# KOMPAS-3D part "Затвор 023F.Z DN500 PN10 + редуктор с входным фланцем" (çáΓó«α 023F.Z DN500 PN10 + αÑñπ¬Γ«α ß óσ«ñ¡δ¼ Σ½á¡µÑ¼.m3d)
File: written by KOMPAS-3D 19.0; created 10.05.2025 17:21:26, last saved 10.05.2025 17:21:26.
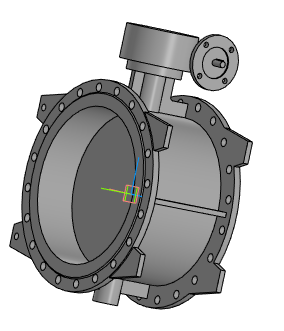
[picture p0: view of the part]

Document properties: Полное имя файла: Затвор 023F.Z DN500 PN10 + редуктор с входным фланцем.a3d

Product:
- Part/product: Затвор 023F.Z DN500 PN10 + редуктор с входным фланцем
    Масса: 260.59

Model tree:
1. Операция без истории:1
